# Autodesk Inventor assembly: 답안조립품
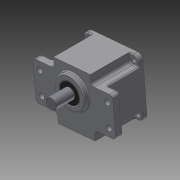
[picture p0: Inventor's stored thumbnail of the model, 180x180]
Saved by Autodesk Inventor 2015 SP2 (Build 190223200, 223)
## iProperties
Created: 2015-06
Part Number: 답안조립품
Document SubType Name: Assembly
Designer: AMC
Author: AMC
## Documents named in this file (12)
- C:\Users\AMC\Desktop\450620V1001\답안조립품.iam
- C:\Users\AMC\Desktop\450620V1001\본체.ipt
- C:\Users\AMC\Desktop\450620V1001\오일실 17x32x8.ipt
- C:\Users\AMC\Desktop\450620V1001\베어링 6003.ipt
- 베어링 6003.ipt
- C:\Users\AMC\Desktop\450620V1001\서브축.ipt
- C:\Users\AMC\Desktop\450620V1001\베어링 608.ipt
- 베어링 608.ipt
- C:\Users\AMC\Desktop\450620V1001\메인축.ipt
- C:\Users\AMC\Desktop\450620V1001\커버.ipt
- C:\Users\AMC\Desktop\450620V1001\오일실 8x22x7.ipt
- C:\Users\AMC\Desktop\450620V1001\M4x0.5x16.ipt
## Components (4 placed, 1 different names)
1. M4x0.5x12:1
2. M4x0.5x12:2
3. M4x0.5x12:3
4. M4x0.5x12:4
